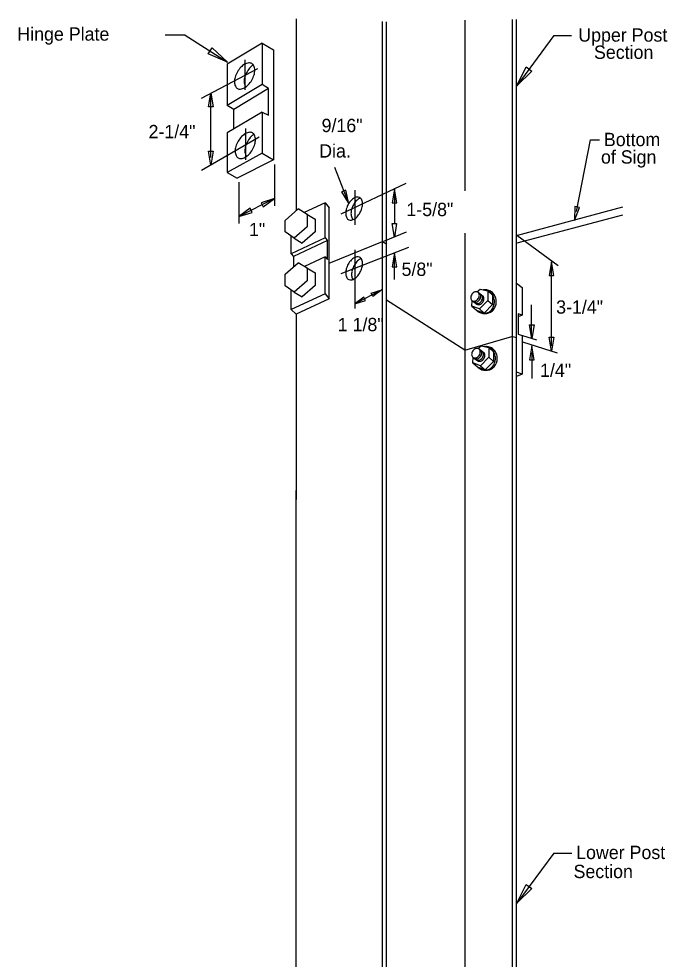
# Model space of a CAD drawing. Extents: x 12.3 to 19.6, y 5.9 to 16.2.
# Drawn here: x 16.261 to 19.184, y 10.993 to 15.233 of the extents above; entities that cross this region are included whole.
import ezdxf

# ---------------------------------------------------------------- set-up
doc = ezdxf.new("R2010")
doc.units = 0
for name, color, linetype in [('DETL-DIMS', 7, 'Continuous'), ('DETL-LINE', 7, 'Continuous'), ('DETL-NOTE', 7, 'Continuous')]:
    doc.layers.add(name, color=color, linetype=linetype)

msp = doc.modelspace()

# ---------------------------------------------------------------- linework, layer by layer
at = {"layer": 'DETL-DIMS'}
for p, q in [((17.0111, 15.1591), (16.9205, 15.1591)), ((17.0111, 15.1591), (17.2014, 15.0374)), ((18.6725, 15.1571), (18.5063, 14.9309)), ((18.6725, 15.1571), (18.7531, 15.1571)), ((17.2802, 15.0475), (17.2802, 14.9134)), ((17.0853, 14.8755), (17.3386, 15.0091)), ((17.1272, 14.6075), (17.1272, 14.8976)), ((17.2834, 14.7379), (17.2834, 14.5977)), ((17.0853, 14.551), (17.3441, 14.7004)), ((18.7746, 14.3637), (18.8387, 14.6879)), ((18.8387, 14.6879), (18.8786, 14.6879)), ((17.413, 14.5762), (17.413, 14.3902)), ((17.7483, 14.4001), (17.6859, 14.5626)), ((17.2532, 14.4964), (17.2532, 14.3104)), ((17.7149, 14.3535), (18.0067, 14.4921)), ((17.7753, 14.4601), (17.7753, 14.3044)), ((17.9543, 14.4666), (17.9543, 14.308)), ((17.413, 14.4227), (17.2532, 14.3422)), ((17.9065, 14.23), (18.0084, 14.273)), ((17.6605, 14.1308), (17.9004, 14.2289)), ((17.7149, 14.0842), (18.02, 14.203)), ((17.7753, 14.1908), (17.7753, 13.9274)), ((17.954, 14.058), (17.954, 14.1777)), ((18.6626, 14.0182), (18.6626, 14.1375)), ((17.8975, 14.0108), (17.7756, 13.9481)), ((18.6626, 13.759), (18.6626, 14.0182)), ((18.573, 13.8056), (18.573, 13.9434)), ((18.5961, 13.7835), (18.5334, 13.8037)), ((18.6892, 13.7248), (18.5331, 13.7749)), ((18.574, 13.729), (18.574, 13.6116)), ((18.6725, 11.4708), (18.5063, 11.2447)), ((18.6725, 11.4708), (18.7544, 11.4708))]:
    msp.add_line(p, q, dxfattribs=at)
for points in [[(17.1154, 15.0756), (17.1323, 15.1017), (17.2023, 15.038)], [(18.548, 15.0158), (18.5733, 14.9977), (18.5063, 14.9309)], [(17.1376, 14.8354), (17.1169, 14.8354), (17.1272, 14.8976)], [(17.1169, 14.6357), (17.1376, 14.6357), (17.1272, 14.5734)], [(17.7357, 14.4611), (17.7164, 14.4536), (17.7487, 14.3994)], [(17.9439, 14.403), (17.9647, 14.403), (17.9543, 14.4652)], [(17.353, 14.404), (17.3623, 14.3854), (17.4132, 14.4228)], [(17.3134, 14.3604), (17.3041, 14.379), (17.253, 14.3421)], [(18.7888, 14.382), (18.7684, 14.386), (18.7667, 14.323)], [(17.9437, 14.3102), (17.9644, 14.3102), (17.954, 14.248)], [(17.9439, 14.1152), (17.9647, 14.1152), (17.9543, 14.1774)], [(18.6522, 14.0753), (18.673, 14.0753), (18.6626, 14.1375)], [(17.8569, 13.9807), (17.8493, 13.9954), (17.8974, 14.0107)], [(17.8237, 13.9626), (17.8164, 13.9775), (17.7755, 13.948)], [(18.563, 13.8532), (18.5838, 13.8532), (18.5734, 13.791)], [(18.6522, 13.7969), (18.673, 13.7969), (18.6626, 13.7347)], [(18.5636, 13.696), (18.5843, 13.696), (18.574, 13.7582)], [(18.548, 11.3296), (18.5733, 11.3115), (18.5063, 11.2447)]]:
    msp.add_lwpolyline(points, close=True, dxfattribs=at)
at = {"layer": 'DETL-LINE'}
for p, q in [((17.5112, 15.2331), (17.5112, 14.3678)), ((18.2711, 15.2266), (18.2711, 14.4578)), ((18.486, 13.1634), (18.486, 15.2297)), ((18.5051, 13.0649), (18.5051, 15.2298)), ((17.9004, 13.059), (17.9004, 15.2207)), ((17.9193, 13.0608), (17.9193, 15.2192)), ((17.3577, 15.1229), (17.201, 15.0292)), ((17.3577, 15.1229), (17.4092, 15.0935)), ((17.3577, 15.1229), (17.3577, 14.9365)), ((17.3577, 15.1229), (17.4092, 15.0935)), ((17.4092, 15.0935), (17.4092, 14.5974)), ((17.201, 15.0292), (17.201, 14.8427)), ((17.2802, 15.0475), (17.2802, 14.9134)), ((17.228, 14.9508), (17.3386, 15.0091)), ((17.3577, 14.9365), (17.201, 14.8427)), ((17.3873, 14.9184), (17.3577, 14.9365)), ((17.3873, 14.9184), (17.3577, 14.9365)), ((17.3873, 14.9184), (17.2306, 14.8247)), ((17.3873, 14.798), (17.3873, 14.9184)), ((17.2306, 14.8247), (17.201, 14.8427)), ((17.3577, 14.8128), (17.201, 14.7191)), ((17.2306, 14.7368), (17.2306, 14.8247)), ((17.3577, 14.8128), (17.3577, 14.6268)), ((17.3577, 14.8128), (17.3873, 14.798)), ((17.201, 14.7191), (17.201, 14.54)), ((17.3577, 14.6268), (17.201, 14.54)), ((17.4092, 14.5974), (17.245, 14.5148)), ((17.3577, 14.6268), (17.4092, 14.5974)), ((17.201, 14.54), (17.245, 14.5148)), ((17.4612, 14.3238), (17.5202, 14.3757)), ((17.5609, 14.3514), (17.5202, 14.3757)), ((17.6415, 14.4038), (17.547, 14.3597)), ((17.6415, 14.2461), (17.6415, 14.4038)), ((17.6415, 14.4038), (17.6605, 14.3811)), ((17.6605, 13.9703), (17.6605, 14.3811)), ((18.5051, 14.256), (18.9848, 14.3852)), ((17.5588, 14.3527), (17.5967, 14.3297)), ((17.5609, 14.3533), (17.5609, 14.2943)), ((18.5073, 14.2223), (18.9848, 14.3488)), ((17.4612, 14.2719), (17.4612, 14.3238)), ((17.5609, 14.2943), (17.5019, 14.2439)), ((17.5967, 14.3315), (17.5967, 14.2726)), ((17.5019, 14.2439), (17.4612, 14.2719)), ((17.4884, 14.1734), (17.4884, 14.2532)), ((17.5967, 14.2726), (17.5378, 14.2221)), ((18.2711, 14.267), (18.2711, 9.8136)), ((18.5064, 14.2577), (18.692, 14.1206)), ((17.6415, 14.2461), (17.4884, 14.1734)), ((17.6523, 14.2333), (17.4992, 14.1606)), ((17.5019, 14.2439), (17.5378, 14.2221)), ((17.6415, 14.2461), (17.6523, 14.2333)), ((17.6523, 14.1473), (17.6523, 14.2333)), ((17.9004, 14.2289), (17.9195, 14.2169)), ((17.4884, 14.1734), (17.4992, 14.1606)), ((17.4612, 14.0812), (17.5202, 14.1331)), ((17.4992, 14.1606), (17.4992, 14.1146)), ((17.5609, 14.1088), (17.5202, 14.1331)), ((17.6415, 14.1602), (17.5487, 14.1161)), ((17.6415, 14.1602), (17.6523, 14.1473)), ((17.6415, 13.993), (17.6415, 14.1602)), ((17.4612, 14.0293), (17.4612, 14.0812)), ((17.5588, 14.1101), (17.5967, 14.087)), ((17.5609, 14.1106), (17.5609, 14.0517)), ((17.5967, 14.0889), (17.5967, 14.0299)), ((17.5609, 14.0517), (17.5019, 14.0012)), ((18.5051, 14.0403), (18.53, 14.0218)), ((17.5019, 14.0012), (17.4612, 14.0293)), ((17.4884, 13.9216), (17.4884, 14.0105)), ((17.6415, 13.993), (17.4884, 13.9216)), ((17.5019, 14.0012), (17.5378, 13.9794)), ((17.5967, 14.0299), (17.5378, 13.9794)), ((17.6415, 13.993), (17.6605, 13.9703)), ((18.3262, 14.0024), (18.3408, 14.0139)), ((18.3314, 14.0002), (18.3549, 13.9821)), ((18.3408, 14.0139), (18.3757, 14.0067)), ((18.3757, 14.0067), (18.3965, 13.9872)), ((18.3757, 14.0067), (18.3757, 13.9636)), ((18.53, 14.0218), (18.53, 13.8967)), ((17.6605, 13.9703), (17.5112, 13.9007)), ((18.2711, 13.7382), (17.9192, 13.9648)), ((18.3033, 13.9374), (18.3049, 13.9617)), ((18.307, 13.9607), (18.3255, 13.9465)), ((18.3757, 13.9636), (18.3382, 13.9247)), ((18.3757, 13.9636), (18.3965, 13.9441)), ((18.3965, 13.9872), (18.3965, 13.9441)), ((17.4884, 13.9216), (17.5112, 13.9007)), ((18.3033, 13.9374), (18.3239, 13.9198)), ((18.3382, 13.9247), (18.3033, 13.9374)), ((18.359, 13.9052), (18.3241, 13.918)), ((18.3382, 13.9247), (18.359, 13.9052)), ((18.3965, 13.9441), (18.359, 13.9052)), ((17.5112, 13.9007), (17.5112, 13.0649)), ((18.5129, 13.9033), (18.5129, 13.8111)), ((18.53, 13.8967), (18.5129, 13.9033)), ((18.53, 13.8967), (18.5129, 13.8893)), ((18.2711, 13.7382), (18.484, 13.8007)), ((18.5051, 13.794), (18.484, 13.8007)), ((18.5129, 13.8111), (18.53, 13.8058)), ((18.53, 13.8058), (18.53, 13.6306)), ((18.3305, 13.7467), (18.3451, 13.7582)), ((18.3357, 13.7445), (18.3592, 13.7264)), ((18.3451, 13.7582), (18.38, 13.751)), ((18.38, 13.751), (18.38, 13.7079)), ((18.38, 13.751), (18.4008, 13.7315)), ((18.3075, 13.6818), (18.3092, 13.7061)), ((18.3113, 13.705), (18.3298, 13.6908)), ((18.38, 13.7079), (18.3424, 13.669)), ((18.38, 13.7079), (18.4008, 13.6885)), ((18.4008, 13.7315), (18.4008, 13.6885)), ((18.3424, 13.669), (18.3075, 13.6818)), ((18.3075, 13.6818), (18.3282, 13.6642)), ((18.3633, 13.6496), (18.3284, 13.6623)), ((18.3424, 13.669), (18.3633, 13.6496)), ((18.4008, 13.6885), (18.3633, 13.6496)), ((18.53, 13.6306), (18.5051, 13.6402)), ((18.53, 13.6306), (18.5051, 13.6208)), ((17.9004, 9.5491), (17.9004, 13.1563)), ((18.486, 10.0267), (18.486, 13.1634)), ((17.5112, 9.6534), (17.5112, 13.1068)), ((17.9193, 9.5567), (17.9193, 13.1351)), ((18.5051, 9.7915), (18.5051, 13.0785))]:
    msp.add_line(p, q, dxfattribs=at)
for centre, radius, start, end in [((17.3435, 14.9378), 0.112, 136.5505, 150), ((17.3435, 14.9378), 0.112, 136.5505, 150), ((17.316, 14.9639), 0.0741, 120, 136.5505), ((17.316, 14.9639), 0.0741, 120, 136.5505), ((17.3026, 14.9871), 0.0473, 95.6571, 120), ((17.3026, 14.9871), 0.0473, 95.6571, 120), ((17.3873, 14.9387), 0.112, 136.5505, 150), ((17.3873, 14.9387), 0.112, 136.5505, 150), ((17.3002, 15.0118), 0.0224, 60, 95.6571), ((17.3002, 15.0118), 0.0224, 60, 95.6571), ((17.3598, 14.9647), 0.0741, 124.5311, 136.5505), ((17.3598, 14.9647), 0.0741, 124.5311, 136.5505), ((17.3002, 15.0118), 0.0224, 24.3429, 60), ((17.3002, 15.0118), 0.0224, 24.3429, 60), ((17.2775, 15.0016), 0.0473, 360, 24.3429), ((17.2775, 15.0016), 0.0473, 360, 24.3429), ((17.3072, 14.9486), 0.0741, 163.4495, 180), ((17.3072, 14.9486), 0.0741, 163.4495, 180), ((17.3435, 14.9378), 0.112, 150, 163.4495), ((17.3435, 14.9378), 0.112, 150, 163.4495), ((17.351, 14.9495), 0.0741, 163.4495, 180), ((17.351, 14.9495), 0.0741, 163.4495, 180), ((17.3873, 14.9387), 0.112, 150, 163.4495), ((17.3873, 14.9387), 0.112, 150, 163.4495), ((17.2144, 15.0124), 0.112, 330, 343.4495), ((17.2144, 15.0124), 0.112, 330, 343.4495), ((17.2507, 15.0016), 0.0741, 343.4495, 0), ((17.2507, 15.0016), 0.0741, 343.4495, 0), ((17.2804, 14.9486), 0.0473, 180, 204.3429), ((17.2804, 14.9486), 0.0473, 180, 204.3429), ((17.2578, 14.9384), 0.0224, 204.3429, 240), ((17.2578, 14.9384), 0.0224, 204.3429, 240), ((17.3242, 14.9495), 0.0473, 180, 204.3429), ((17.3242, 14.9495), 0.0473, 180, 204.3429), ((17.2419, 14.9863), 0.0741, 300, 316.5505), ((17.2419, 14.9863), 0.0741, 300, 316.5505), ((17.3015, 14.9392), 0.0224, 204.3429, 218.3923), ((17.3015, 14.9392), 0.0224, 204.3429, 218.3923), ((17.2144, 15.0124), 0.112, 316.5505, 330), ((17.2144, 15.0124), 0.112, 316.5505, 330), ((17.2578, 14.9384), 0.0224, 240, 275.6571), ((17.2578, 14.9384), 0.0224, 240, 275.6571), ((17.2553, 14.9631), 0.0473, 275.6571, 300), ((17.2553, 14.9631), 0.0473, 275.6571, 300), ((17.3192, 14.6509), 0.0741, 120, 136.5505), ((17.3058, 14.6741), 0.0473, 95.6571, 120), ((17.3034, 14.6988), 0.0224, 60, 95.6571), ((17.3034, 14.6988), 0.0224, 24.3429, 60), ((17.3467, 14.6248), 0.112, 150, 163.4495), ((17.3467, 14.6248), 0.112, 136.5505, 150), ((17.3904, 14.6257), 0.112, 150, 163.4495), ((17.3904, 14.6257), 0.112, 136.5505, 150), ((17.363, 14.6517), 0.0741, 124.5311, 136.5505), ((17.2807, 14.6886), 0.0473, 360, 24.3429), ((17.2539, 14.6886), 0.0741, 343.4495, 0), ((17.3104, 14.6356), 0.0741, 163.4495, 180), ((17.2836, 14.6356), 0.0473, 180, 204.3429), ((17.3542, 14.6365), 0.0741, 163.4495, 180), ((17.3274, 14.6365), 0.0473, 180, 204.3429), ((17.2176, 14.6994), 0.112, 316.5505, 330), ((17.2176, 14.6994), 0.112, 330, 343.4495), ((17.2609, 14.6254), 0.0224, 204.3429, 240), ((17.2609, 14.6254), 0.0224, 240, 275.6571), ((17.2585, 14.6501), 0.0473, 275.6571, 300), ((17.2451, 14.6733), 0.0741, 300, 316.5505), ((17.3047, 14.6262), 0.0224, 204.3429, 218.3923), ((17.8053, 14.3699), 0.0639, 124.299, 140.8496), ((17.7922, 14.389), 0.0408, 99.9562, 124.299), ((17.829, 14.3685), 0.0639, 124.299, 140.8496), ((17.7885, 14.4101), 0.0194, 64.299, 99.9562), ((17.816, 14.3876), 0.0408, 112.3204, 124.299), ((17.7885, 14.4101), 0.0194, 28.6419, 64.299), ((17.7697, 14.3999), 0.0408, 4.299, 28.6419), ((17.8306, 14.3493), 0.0966, 154.299, 167.7485), ((17.8306, 14.3493), 0.0966, 140.8496, 154.299), ((17.8543, 14.3479), 0.0966, 154.299, 167.7485), ((17.8543, 14.3479), 0.0966, 140.8496, 154.299), ((17.7147, 14.4051), 0.0966, 334.299, 347.7485), ((17.7467, 14.3981), 0.0639, 347.7485, 4.299), ((17.7987, 14.3562), 0.0639, 167.7485, 184.299), ((17.7756, 14.3545), 0.0408, 184.299, 208.6419), ((17.7568, 14.3442), 0.0194, 208.6419, 244.299), ((17.8224, 14.3548), 0.0639, 167.7485, 184.299), ((17.7994, 14.3531), 0.0408, 184.299, 208.6419), ((17.7805, 14.3428), 0.0194, 208.6419, 231.8674), ((17.7401, 14.3844), 0.0639, 304.299, 320.8496), ((17.7147, 14.4051), 0.0966, 320.8496, 334.299), ((17.7568, 14.3442), 0.0194, 244.299, 279.9562), ((17.7531, 14.3654), 0.0408, 279.9562, 304.299), ((17.8306, 14.08), 0.0966, 154.299, 167.7485), ((17.8306, 14.08), 0.0966, 154.299, 167.7485), ((17.8306, 14.08), 0.0966, 140.8496, 154.299), ((17.8306, 14.08), 0.0966, 140.8496, 154.299), ((17.8053, 14.1006), 0.0639, 124.299, 140.8496), ((17.8053, 14.1006), 0.0639, 124.299, 140.8496), ((17.7922, 14.1197), 0.0408, 99.9562, 124.299), ((17.7922, 14.1197), 0.0408, 99.9562, 124.299), ((17.857, 14.0739), 0.0966, 140.8496, 154.299), ((17.8317, 14.0945), 0.0639, 124.299, 140.8496), ((17.7885, 14.1408), 0.0194, 64.299, 99.9562), ((17.7885, 14.1408), 0.0194, 64.299, 99.9562), ((17.8187, 14.1136), 0.0408, 110.4142, 124.299), ((17.7885, 14.1408), 0.0194, 28.6419, 64.299), ((17.7885, 14.1408), 0.0194, 28.6419, 64.299), ((17.7697, 14.1306), 0.0408, 4.299, 28.6419), ((17.7697, 14.1306), 0.0408, 4.299, 28.6419), ((17.7467, 14.1288), 0.0639, 347.7485, 4.299), ((17.7467, 14.1288), 0.0639, 347.7485, 4.299), ((17.7987, 14.0869), 0.0639, 167.7485, 184.299), ((17.7987, 14.0869), 0.0639, 167.7485, 184.299), ((17.7756, 14.0852), 0.0408, 184.299, 208.6419), ((17.7756, 14.0852), 0.0408, 184.299, 208.6419), ((17.8251, 14.0808), 0.0639, 167.7485, 184.299), ((17.8251, 14.0808), 0.0639, 167.7485, 184.299), ((17.857, 14.0739), 0.0966, 154.299, 167.7485), ((17.857, 14.0739), 0.0966, 154.299, 167.7485), ((17.7147, 14.1357), 0.0966, 320.8496, 334.299), ((17.7147, 14.1357), 0.0966, 320.8496, 334.299), ((17.7147, 14.1357), 0.0966, 334.299, 347.7485), ((17.7147, 14.1357), 0.0966, 334.299, 347.7485), ((17.7568, 14.0749), 0.0194, 208.6419, 244.299), ((17.7568, 14.0749), 0.0194, 208.6419, 244.299), ((17.7568, 14.0749), 0.0194, 244.299, 279.9562), ((17.7568, 14.0749), 0.0194, 244.299, 279.9562), ((17.7531, 14.096), 0.0408, 279.9562, 304.299), ((17.7531, 14.096), 0.0408, 279.9562, 304.299), ((17.8021, 14.0791), 0.0408, 184.299, 208.6419), ((17.8021, 14.0791), 0.0408, 184.299, 208.6419), ((17.7832, 14.0688), 0.0194, 208.6419, 214.6956), ((17.7832, 14.0688), 0.0194, 208.6419, 214.6956), ((17.7401, 14.1151), 0.0639, 304.299, 320.8496), ((17.7401, 14.1151), 0.0639, 304.299, 320.8496), ((18.3291, 13.9732), 0.0312, 127.7776, 144.9363), ((18.3248, 13.9788), 0.0241, 108.2349, 127.7776), ((18.3231, 13.9839), 0.0187, 83.9964, 108.2349), ((18.3237, 13.9895), 0.0131, 54.9363, 83.9964), ((18.3237, 13.9895), 0.0131, 25.8762, 54.9363), ((18.3186, 13.9871), 0.0187, 1.6377, 25.8762), ((18.3577, 13.9676), 0.043, 90, 91.3028), ((18.3577, 13.9676), 0.043, 65.2453, 90), ((18.3657, 13.9676), 0.043, 90, 95.3435), ((18.3657, 13.9676), 0.043, 65.2453, 90), ((18.3554, 13.9627), 0.0485, 41.9335, 65.2453), ((18.3634, 13.9627), 0.0485, 41.9335, 65.2453), ((18.3519, 13.9595), 0.0532, 20.4097, 41.9335), ((18.3599, 13.9595), 0.0532, 20.4097, 41.9335), ((18.3224, 13.9754), 0.0241, 162.095, 181.6377), ((18.317, 13.9753), 0.0187, 181.6377, 205.8762), ((18.3291, 13.9732), 0.0312, 144.9363, 162.095), ((18.3119, 13.9728), 0.0131, 205.8762, 234.9363), ((18.3119, 13.9728), 0.0131, 234.9363, 263.9964), ((18.3125, 13.9784), 0.0187, 263.9964, 288.2349), ((18.3185, 13.968), 0.0131, 234.9363, 263.9964), ((18.3191, 13.9735), 0.0187, 263.9964, 288.2349), ((18.3109, 13.9835), 0.0241, 288.2349, 307.7776), ((18.3265, 13.9618), 0.0131, 234.9363, 263.9964), ((18.3174, 13.9786), 0.0241, 288.2349, 307.7776), ((18.3065, 13.9891), 0.0312, 307.7776, 324.9363), ((18.3065, 13.9891), 0.0312, 324.9363, 342.095), ((18.3131, 13.9842), 0.0312, 307.7776, 324.9363), ((18.3255, 13.9724), 0.0241, 288.2349, 307.7776), ((18.3133, 13.9869), 0.0241, 342.095, 1.6377), ((18.3131, 13.9842), 0.0312, 324.9363, 342.095), ((18.3211, 13.978), 0.0312, 307.7776, 324.9363), ((18.3303, 13.9847), 0.0131, 25.8762, 37.6651), ((18.3252, 13.9822), 0.0187, 1.6377, 25.8762), ((18.3198, 13.9821), 0.0241, 342.095, 1.6377), ((18.3273, 13.9737), 0.0312, 307.7776, 324.9363), ((18.3211, 13.978), 0.0312, 324.9363, 342.095), ((18.3383, 13.9785), 0.0131, 25.8762, 37.6651), ((18.3332, 13.976), 0.0187, 1.6377, 25.8762), ((18.3279, 13.9759), 0.0241, 342.095, 1.6377), ((18.3273, 13.9737), 0.0312, 324.9363, 342.095), ((18.3445, 13.9741), 0.0131, 25.8762, 37.6651), ((18.3394, 13.9716), 0.0187, 1.6377, 25.8762), ((18.3341, 13.9715), 0.0241, 342.095, 1.6377), ((18.3463, 13.9574), 0.0591, 0, 20.4097), ((18.3463, 13.9574), 0.0591, 339.5903, 360), ((18.3544, 13.9574), 0.0591, 0, 20.4097), ((18.3544, 13.9574), 0.0591, 339.5903, 360), ((18.3328, 13.9574), 0.0131, 228.7186, 234.9363), ((18.3271, 13.9673), 0.0187, 263.9964, 288.2349), ((18.3328, 13.9574), 0.0131, 234.9363, 263.9964), ((18.3599, 13.9522), 0.0485, 226.4794, 245.2453), ((18.3333, 13.963), 0.0187, 263.9964, 288.2349), ((18.3317, 13.9681), 0.0241, 288.2349, 307.7776), ((18.3577, 13.9473), 0.043, 245.2453, 270), ((18.3577, 13.9473), 0.043, 270, 294.7547), ((18.3657, 13.9473), 0.043, 270, 294.7547), ((18.3554, 13.9522), 0.0485, 294.7547, 318.0665), ((18.3634, 13.9522), 0.0485, 294.7547, 318.0665), ((18.3519, 13.9554), 0.0532, 318.0665, 339.5903), ((18.3599, 13.9554), 0.0532, 318.0665, 339.5903), ((18.3657, 13.9473), 0.043, 264.6565, 270), ((18.3334, 13.7176), 0.0312, 127.7776, 144.9363), ((18.3291, 13.7232), 0.0241, 108.2349, 127.7776), ((18.3274, 13.7283), 0.0187, 83.9964, 108.2349), ((18.328, 13.7338), 0.0131, 54.9363, 83.9964), ((18.328, 13.7338), 0.0131, 25.8762, 54.9363), ((18.3229, 13.7314), 0.0187, 1.6377, 25.8762), ((18.362, 13.7119), 0.043, 90, 91.3028), ((18.362, 13.7119), 0.043, 65.2453, 90), ((18.37, 13.7119), 0.043, 90, 95.3435), ((18.37, 13.7119), 0.043, 65.2453, 90), ((18.3597, 13.707), 0.0485, 41.9335, 65.2453), ((18.3677, 13.707), 0.0485, 41.9335, 65.2453), ((18.3562, 13.7038), 0.0532, 20.4097, 41.9335), ((18.3642, 13.7038), 0.0532, 20.4097, 41.9335), ((18.3267, 13.7197), 0.0241, 162.095, 181.6377), ((18.3213, 13.7196), 0.0187, 181.6377, 205.8762), ((18.3334, 13.7176), 0.0312, 144.9363, 162.095), ((18.3162, 13.7171), 0.0131, 205.8762, 234.9363), ((18.3162, 13.7171), 0.0131, 234.9363, 263.9964), ((18.3168, 13.7227), 0.0187, 263.9964, 288.2349), ((18.3228, 13.7123), 0.0131, 234.9363, 263.9964), ((18.3234, 13.7179), 0.0187, 263.9964, 288.2349), ((18.3152, 13.7278), 0.0241, 288.2349, 307.7776), ((18.3217, 13.723), 0.0241, 288.2349, 307.7776), ((18.3108, 13.7334), 0.0312, 307.7776, 324.9363), ((18.3108, 13.7334), 0.0312, 324.9363, 342.095), ((18.3174, 13.7286), 0.0312, 307.7776, 324.9363), ((18.3298, 13.7168), 0.0241, 288.2349, 307.7776), ((18.3176, 13.7312), 0.0241, 342.095, 1.6377), ((18.3174, 13.7286), 0.0312, 324.9363, 342.095), ((18.3254, 13.7224), 0.0312, 307.7776, 324.9363), ((18.3345, 13.729), 0.0131, 25.8762, 37.6651), ((18.3295, 13.7265), 0.0187, 1.6377, 25.8762), ((18.3241, 13.7264), 0.0241, 342.095, 1.6377), ((18.3316, 13.718), 0.0312, 307.7776, 324.9363), ((18.3254, 13.7224), 0.0312, 324.9363, 342.095), ((18.3426, 13.7228), 0.0131, 25.8762, 37.6651), ((18.3375, 13.7203), 0.0187, 1.6377, 25.8762), ((18.3322, 13.7202), 0.0241, 342.095, 1.6377), ((18.3316, 13.718), 0.0312, 324.9363, 342.095), ((18.3488, 13.7184), 0.0131, 25.8762, 37.6651), ((18.3437, 13.716), 0.0187, 1.6377, 25.8762), ((18.3384, 13.7158), 0.0241, 342.095, 1.6377), ((18.3506, 13.7018), 0.0591, 360, 20.4097), ((18.3506, 13.7018), 0.0591, 339.5903, 0), ((18.3587, 13.7018), 0.0591, 360, 20.4097), ((18.3587, 13.7018), 0.0591, 339.5903, 0), ((18.3308, 13.7061), 0.0131, 234.9363, 263.9964), ((18.337, 13.7017), 0.0131, 228.7186, 234.9363), ((18.3314, 13.7117), 0.0187, 263.9964, 288.2349), ((18.337, 13.7017), 0.0131, 234.9363, 263.9964), ((18.3642, 13.6965), 0.0485, 226.4794, 245.2453), ((18.3376, 13.7073), 0.0187, 263.9964, 288.2349), ((18.336, 13.7124), 0.0241, 288.2349, 307.7776), ((18.3597, 13.6965), 0.0485, 294.7547, 318.0665), ((18.3677, 13.6965), 0.0485, 294.7547, 318.0665), ((18.3562, 13.6997), 0.0532, 318.0665, 339.5903), ((18.3642, 13.6997), 0.0532, 318.0665, 339.5903), ((18.362, 13.6916), 0.043, 245.2453, 270), ((18.362, 13.6916), 0.043, 270, 294.7547), ((18.37, 13.6916), 0.043, 264.6565, 270), ((18.37, 13.6916), 0.043, 270, 294.7547)]:
    msp.add_arc(centre, radius, start, end, dxfattribs=at)

# ---------------------------------------------------------------- texts
at = {"layer": 'DETL-NOTE'}
for s, p in [('Hinge Plate', (16.2544, 15.1345)), ('Upper Post', (18.7833, 15.13)), ('Section', (18.8541, 15.0524)), ('2-1/4"', (16.8459, 14.6946)), ('9/16"', (17.6261, 14.7222)), ('Bottom', (18.8987, 14.659)), ('Dia.', (17.6152, 14.6075)), ('of Sign', (18.8856, 14.5801)), ('1-5/8"', (18.0085, 14.3434)), ('1"', (17.2989, 14.253)), ('5/8"', (17.9865, 14.0737)), ('3-1/4"', (18.6835, 13.9035)), ('1 1/8"', (17.6989, 13.8244)), ('1/4"', (18.6111, 13.6183)), ('Lower Post', (18.7737, 11.4443)), ('Section', (18.7619, 11.3584))]:
    msp.add_text(s, height=0.06, dxfattribs=at).set_placement(p)

doc.saveas('drawing.dxf')
